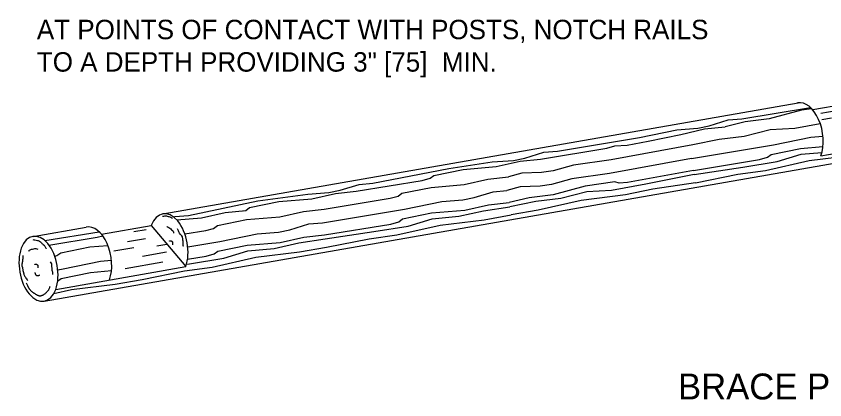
# Model space of a CAD drawing. Extents: x 49991 to 50288, y 49919 to 50011.
# Drawn here: x 50020.922 to 50023.528, y 49985.917 to 49987.153 of the extents above; entities that cross this region are included whole.
import ezdxf

# ---------------------------------------------------------------- set-up
doc = ezdxf.new("R2010")
doc.units = 0
doc.layers.add('Level 1', color=7, linetype='Continuous')
doc.layers.add('Level 2', color=7, linetype='Continuous')

msp = doc.modelspace()

# ---------------------------------------------------------------- linework, layer by layer
at = {"layer": 'Level 1'}
for p, q in [((50021.01237431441, 49986.23456588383), (50026.27076893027, 49987.15270974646)), ((50021.39464107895, 49986.51584634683), (50023.44173309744, 49986.873468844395)), ((50023.65085953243, 49986.878920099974), (50023.48937606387, 49986.850725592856)), ((50023.65298090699, 49986.863473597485), (50023.51549670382, 49986.839411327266)), ((50023.549503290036, 49986.82367427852), (50023.51885112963, 49986.81836657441)), ((50023.51548171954, 49986.702846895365), (50023.76174656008, 49986.745867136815)), ((50020.97702824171, 49986.44337197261), (50021.147483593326, 49986.473151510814)), ((50021.196921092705, 49986.45022108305), (50021.357590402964, 49986.47828976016)), ((50021.357590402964, 49986.47828976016), (50021.46864324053, 49986.34571894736)), ((50021.301555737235, 49986.45871434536), (50021.34095291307, 49986.4656606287)), ((50021.28090016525, 49986.42621710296), (50021.33879660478, 49986.436373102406)), ((50021.37569190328, 49986.412992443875), (50021.40757901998, 49986.41861501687)), ((50021.23709514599, 49986.39673294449), (50021.30092255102, 49986.407883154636)), ((50021.32977004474, 49986.37982644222), (50021.406914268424, 49986.39330485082)), ((50021.04959695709, 49986.272512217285), (50021.46864324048, 49986.34571894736)), ((50021.27350002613, 49986.339785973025), (50021.39434734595, 49986.36100572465))]:
    msp.add_line(p, q, dxfattribs=at)
for points in [[(50023.48609654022, 49986.854358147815), (50023.45255549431, 49986.8495782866), (50023.34908352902, 49986.82180914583), (50023.27121411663, 49986.81229836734), (50023.20670810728, 49986.79626866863)], [(50023.26098381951, 49986.82190900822), (50023.482077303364, 49986.85843118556)], [(50022.66652195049, 49986.71817836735), (50022.93076741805, 49986.76176230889), (50023.05090739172, 49986.78677876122), (50023.11917129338, 49986.79196925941), (50023.15539182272, 49986.799551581), (50023.2167627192, 49986.818467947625), (50023.26098381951, 49986.82190900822)], [(50022.61215795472, 49986.69239057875), (50022.825438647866, 49986.727613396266), (50022.85113049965, 49986.734753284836), (50022.89068484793, 49986.737631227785), (50022.95827289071, 49986.74997057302), (50023.06399196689, 49986.772005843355), (50023.14047937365, 49986.78945901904), (50023.20670810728, 49986.79626866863)], [(50023.513478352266, 49986.80624281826), (50023.431741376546, 49986.79107544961), (50023.35156822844, 49986.78674985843), (50023.26799229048, 49986.765031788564), (50023.18723492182, 49986.75504675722), (50023.10318851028, 49986.73849789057)], [(50023.097965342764, 49986.69451279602), (50023.36220367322, 49986.7381651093), (50023.482507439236, 49986.76326777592), (50023.522079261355, 49986.7662235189)], [(50023.10318851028, 49986.73849789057), (50022.83977171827, 49986.689954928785), (50022.717983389, 49986.67278395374), (50022.65226282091, 49986.6544848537), (50022.61556240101, 49986.649513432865), (50022.55150657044, 49986.646386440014), (50022.50870316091, 49986.634661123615)], [(50023.104696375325, 49986.65585343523), (50023.31792297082, 49986.69093237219), (50023.34361482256, 49986.69807226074), (50023.35560455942, 49986.707030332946), (50023.44973187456, 49986.72632486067), (50023.52209478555, 49986.73247231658)], [(50022.071975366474, 49986.61426609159), (50022.31611041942, 49986.662230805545), (50022.45648684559, 49986.682983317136), (50022.52468594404, 49986.68813249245), (50022.56093709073, 49986.69575256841), (50022.62216767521, 49986.71468884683), (50022.66652195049, 49986.71817836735)], [(50023.10690498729, 49986.642640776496), (50023.263635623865, 49986.666396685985), (50023.37449895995, 49986.6846044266), (50023.4514986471, 49986.707744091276), (50023.5188752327, 49986.713935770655)], [(50023.111541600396, 49986.61610012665), (50023.24813982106, 49986.64335295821), (50023.337355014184, 49986.655741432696), (50023.4776308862, 49986.68749060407), (50023.61869119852, 49986.70477258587), (50023.70588306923, 49986.71999099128)], [(50022.017604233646, 49986.58854667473), (50022.23091554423, 49986.62380724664), (50022.25661096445, 49986.630912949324), (50022.2686078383, 49986.63980264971), (50022.36263616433, 49986.65905228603), (50022.469479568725, 49986.66809713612), (50022.54603534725, 49986.68555744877), (50022.61215795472, 49986.69239057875)], [(50023.097965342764, 49986.69451279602), (50022.83452150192, 49986.64589789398), (50022.71279797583, 49986.62876824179), (50022.6470396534, 49986.6104997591), (50022.610308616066, 49986.6054905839), (50022.54634463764, 49986.60247685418), (50022.5035248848, 49986.59057703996)], [(50023.104696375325, 49986.65585343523), (50022.8921515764, 49986.61656043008), (50022.86550708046, 49986.61457397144), (50022.85132864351, 49986.618968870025), (50022.75617881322, 49986.60516606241), (50022.652741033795, 49986.57740049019), (50022.57479968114, 49986.5679167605), (50022.51032072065, 49986.55195900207)], [(50021.91419789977, 49986.5306840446), (50022.127399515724, 49986.56600228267), (50022.153204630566, 49986.57305031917), (50022.16508824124, 49986.58203187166), (50022.25926044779, 49986.6012274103), (50022.36603548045, 49986.61026512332), (50022.442553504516, 49986.627756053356), (50022.50870316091, 49986.634661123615)], [(50023.10690498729, 49986.642640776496), (50022.95162023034, 49986.61198588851), (50022.84113986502, 49986.59143359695), (50022.76089834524, 49986.587100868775), (50022.677397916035, 49986.56532156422), (50022.59652728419, 49986.55542838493), (50022.51259413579, 49986.538787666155)], [(50021.47742164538, 49986.510422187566), (50021.700740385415, 49986.557286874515), (50021.86194026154, 49986.57907104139), (50021.93020059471, 49986.58429572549), (50021.96637980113, 49986.591942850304), (50022.027658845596, 49986.61074595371), (50022.071975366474, 49986.61426609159)], [(50023.111541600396, 49986.61610012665), (50022.97393627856, 49986.59551560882), (50022.88565831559, 49986.57679711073), (50022.743073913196, 49986.55921780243), (50022.604442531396, 49986.52760573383), (50022.51718585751, 49986.512346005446)], [(50021.65561845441, 49986.52518738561), (50021.66219755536, 49986.527049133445), (50021.67416024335, 49986.5359352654), (50021.76815795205, 49986.55514714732), (50021.87492941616, 49986.56421904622), (50021.95151224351, 49986.58175129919), (50022.017604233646, 49986.58854667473)], [(50021.9092033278, 49986.486826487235), (50022.173312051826, 49986.53039615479), (50022.29361224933, 49986.55553300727), (50022.36177002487, 49986.56074698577), (50022.398058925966, 49986.56833644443), (50022.45929664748, 49986.5872043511), (50022.5035248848, 49986.59057703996)], [(50021.91591088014, 49986.448061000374), (50022.12900073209, 49986.483125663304), (50022.15480791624, 49986.4904849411), (50022.16661958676, 49986.49949354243), (50022.260757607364, 49986.518685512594), (50022.36754691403, 49986.527586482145), (50022.44417106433, 49986.54505393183), (50022.51032072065, 49986.55195900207)], [(50021.43980093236, 49986.496058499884), (50021.519484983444, 49986.50275212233), (50021.596026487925, 49986.52034917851), (50021.66219755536, 49986.527049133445)], [(50021.46565793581, 49986.45096337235), (50021.53285293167, 49986.46209000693), (50021.55855192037, 49986.469161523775), (50021.57057941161, 49986.478088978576), (50021.664668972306, 49986.49741412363), (50021.77144043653, 49986.50648602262), (50021.848003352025, 49986.52387796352), (50021.91419789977, 49986.5306840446)], [(50021.918135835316, 49986.4350228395), (50022.07462360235, 49986.458787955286), (50022.185625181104, 49986.47666454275), (50022.262644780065, 49986.49994451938), (50022.34844153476, 49986.508001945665), (50022.42799139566, 49986.52591303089), (50022.51259413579, 49986.538787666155)], [(50021.42918031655, 49986.5057666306), (50021.43313217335, 49986.50697398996), (50021.47742164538, 49986.510422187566)], [(50021.92270407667, 49986.408475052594), (50022.05917269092, 49986.43564523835), (50022.148607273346, 49986.44791838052), (50022.28880049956, 49986.47979715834), (50022.42996336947, 49986.49708984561), (50022.51718585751, 49986.512346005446)], [(50021.47504547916, 49986.40936738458), (50021.57889150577, 49986.42660071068), (50021.69925650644, 49986.45177888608), (50021.76740150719, 49986.45678418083), (50021.80366899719, 49986.46457875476), (50021.864917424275, 49986.48334410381), (50021.9092033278, 49986.486826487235)], [(50021.0146080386, 49986.42954659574), (50021.18924756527, 49986.45836434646)], [(50021.0275168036, 49986.41532338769), (50021.182739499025, 49986.44092418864), (50021.20113320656, 49986.44481405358)], [(50021.47441530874, 49986.36950321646), (50021.534672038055, 49986.37944348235), (50021.560291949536, 49986.38661041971), (50021.57232657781, 49986.39546950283), (50021.666358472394, 49986.414684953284), (50021.773156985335, 49986.42382879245), (50021.849685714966, 49986.44121716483), (50021.91591088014, 49986.448061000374)], [(50021.471093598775, 49986.35343692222), (50021.48032345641, 49986.35483228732), (50021.59126586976, 49986.37294460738), (50021.6682548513, 49986.39618682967), (50021.754024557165, 49986.40417231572), (50021.83354380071, 49986.42204564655), (50021.918135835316, 49986.4350228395)], [(50021.04643401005, 49986.379242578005), (50021.053707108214, 49986.38125052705), (50021.06562490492, 49986.39023564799), (50021.159755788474, 49986.40949598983), (50021.21761705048, 49986.41436088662)], [(50021.32834476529, 49986.30475511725), (50021.46483479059, 49986.33172018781), (50021.55426937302, 49986.34399332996), (50021.69440700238, 49986.37607365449), (50021.83544383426, 49986.39324951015), (50021.92270407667, 49986.408475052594)], [(50021.05618481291, 49986.335953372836), (50021.073956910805, 49986.33888769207), (50021.19426781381, 49986.363921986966), (50021.229203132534, 49986.36660109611)], [(50021.0558551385, 49986.29909710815), (50021.067415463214, 49986.30786261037), (50021.161621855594, 49986.327061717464), (50021.22931728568, 49986.33278906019)], [(50021.04355354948, 49986.25935074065), (50021.10002777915, 49986.27221340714), (50021.241262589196, 49986.289479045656), (50021.32834476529, 49986.30475511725)]]:
    msp.add_lwpolyline(points, dxfattribs=at)
for centre, major_axis, ratio, start_param, end_param in [((50023.45999035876, 49986.769206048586), (-0.01831237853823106, 0.10428811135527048), 0.577493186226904, 3.925707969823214, 6.306125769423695), ((50021.41297472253, 49986.41161520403), (-0.01831237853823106, 0.10428811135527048), 0.577493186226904, 3.9315222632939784, 7.063530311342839), ((50021.167172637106, 49986.36913342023), (-0.01831237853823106, 0.10428811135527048), 0.577493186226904, 3.9254893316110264, 6.306125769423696), ((50020.994103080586, 49986.338889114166), (-0.01831237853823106, 0.10428811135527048), 0.577493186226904, 3.9256121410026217, 7.063370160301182), ((50020.99409216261, 49986.33885928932), (-0.018312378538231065, 0.10428811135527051), 0.5774931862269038, 0.7858875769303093, 3.9259797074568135)]:
    msp.add_ellipse(centre, major_axis=major_axis, ratio=ratio, start_param=start_param, end_param=end_param, dxfattribs=at)
for points in [[(50021.4262607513, 49986.49996708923), (50021.42279505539, 49986.50337218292), (50021.41277694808, 49986.506646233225), (50021.4071849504, 49986.508239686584), (50021.400074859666, 49986.50815410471), (50021.393523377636, 49986.50702096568)], [(50021.407833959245, 49986.47454390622), (50021.40970440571, 49986.47384063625), (50021.41766929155, 49986.47004123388), (50021.42319306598, 49986.4644664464), (50021.42794747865, 49986.459640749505), (50021.42944595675, 49986.453231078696)], [(50021.46131367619, 49986.41014571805), (50021.461186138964, 49986.41037431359), (50021.46063122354, 49986.42396694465), (50021.459334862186, 49986.431088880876), (50021.45804135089, 49986.441494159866), (50021.448748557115, 49986.45337983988), (50021.444344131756, 49986.46346038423), (50021.441841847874, 49986.46789912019)], [(50020.97638882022, 49986.43293535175), (50020.98261814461, 49986.431857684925), (50020.99049495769, 49986.43022626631), (50020.99501291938, 49986.4286589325), (50021.00006244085, 49986.42597210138), (50021.00344549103, 49986.4226966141), (50021.00680656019, 49986.4189695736), (50021.011951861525, 49986.41470305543), (50021.01360741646, 49986.41307883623), (50021.01587867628, 49986.409860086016), (50021.01812381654, 49986.40556729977), (50021.018671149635, 49986.403965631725)], [(50021.415862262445, 49986.42805861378), (50021.41618418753, 49986.42833690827), (50021.41635143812, 49986.42847472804), (50021.41643673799, 49986.428543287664), (50021.416523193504, 49986.42861160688), (50021.416780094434, 49986.42879039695), (50021.41704695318, 49986.428934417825), (50021.41760567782, 49986.42912878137), (50021.4187890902, 49986.42921720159), (50021.419995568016, 49986.42904693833), (50021.420583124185, 49986.428917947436), (50021.42114724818, 49986.42878806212), (50021.42152562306, 49986.42869908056), (50021.421901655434, 49986.42859872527), (50021.422642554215, 49986.42834220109), (50021.4233616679, 49986.42797510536), (50021.42371046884, 49986.427736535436), (50021.42388172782, 49986.42760112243), (50021.424050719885, 49986.427454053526), (50021.42448148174, 49986.42703870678), (50021.424871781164, 49986.42661233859), (50021.425516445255, 49986.42571975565), (50021.425955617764, 49986.42476273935), (50021.426089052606, 49986.4242558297), (50021.426160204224, 49986.42372772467), (50021.42622673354, 49986.42247789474), (50021.42624951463, 49986.421233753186), (50021.42623392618, 49986.419992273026), (50021.426185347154, 49986.4187504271), (50021.42614881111, 49986.41799255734), (50021.42611281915, 49986.41723475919), (50021.42607205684, 49986.416477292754), (50021.42602120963, 49986.41572041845)], [(50020.96197074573, 49986.39597049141), (50020.963600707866, 49986.39712651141), (50020.971208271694, 49986.401598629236), (50020.97892007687, 49986.40305410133), (50020.985580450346, 49986.40429152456), (50020.9917302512, 49986.401944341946)], [(50020.94415452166, 49986.38125041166), (50020.94408022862, 49986.377368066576), (50020.9440206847, 49986.37543090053), (50020.94385679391, 49986.3735020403), (50020.943075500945, 49986.367519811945), (50020.94223622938, 49986.3615484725), (50020.94171387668, 49986.35894275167), (50020.94105784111, 49986.356352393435), (50020.94050298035, 49986.353751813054), (50020.94033688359, 49986.35243969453), (50020.94029451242, 49986.35177927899), (50020.94028415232, 49986.3511154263), (50020.94057045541, 49986.34875185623), (50020.941213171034, 49986.3464399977), (50020.94196237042, 49986.344140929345), (50020.942298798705, 49986.34298402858), (50020.94256812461, 49986.34181572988), (50020.943358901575, 49986.337509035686), (50020.94415824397, 49986.33320388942), (50020.94555715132, 49986.32653750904), (50020.946390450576, 49986.323232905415), (50020.946860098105, 49986.321591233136), (50020.947372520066, 49986.319957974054), (50020.94925439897, 49986.31565872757), (50020.95172812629, 49986.311669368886), (50020.95910051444, 49986.30096556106)], [(50020.98240673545, 49986.35315038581), (50020.98245611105, 49986.353189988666), (50020.98254256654, 49986.353258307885), (50020.98279946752, 49986.35343709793), (50020.98306632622, 49986.3535811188), (50020.98362505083, 49986.35377548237), (50020.98391490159, 49986.35383108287), (50020.984209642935, 49986.35386568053), (50020.98480846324, 49986.353863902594), (50020.98511504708, 49986.35383402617), (50020.985417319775, 49986.35379729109), (50020.98571678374, 49986.35375129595), (50020.986014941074, 49986.35369363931), (50020.98660249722, 49986.353564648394), (50020.98716662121, 49986.35343476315), (50020.9875449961, 49986.353345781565), (50020.98792102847, 49986.3532454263), (50020.98866192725, 49986.352988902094), (50020.989381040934, 49986.352621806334), (50020.98972984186, 49986.35238323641), (50020.98990110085, 49986.352247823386), (50020.99007009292, 49986.3521007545), (50020.9905008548, 49986.35168540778), (50020.99089115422, 49986.35125903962), (50020.9912314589, 49986.35082731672), (50020.991387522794, 49986.35060080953), (50020.99153581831, 49986.35036645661), (50020.99178228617, 49986.34989950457), (50020.9919749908, 49986.34940944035), (50020.992108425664, 49986.34890253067), (50020.99217957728, 49986.3483744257), (50020.99224610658, 49986.34712459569), (50020.99226888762, 49986.34588045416), (50020.99225329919, 49986.344638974), (50020.99220472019, 49986.34339712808), (50020.992168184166, 49986.34263925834), (50020.99213219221, 49986.34188146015), (50020.992112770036, 49986.341502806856)], [(50021.03992094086, 49986.32057874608), (50021.040440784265, 49986.32532156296), (50021.03927663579, 49986.33030649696), (50021.03770640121, 49986.34237235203), (50021.03746867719, 49986.345569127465), (50021.0367895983, 49986.35485007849), (50021.03291129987, 49986.361177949)], [(50020.99700456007, 49986.31829528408), (50020.99678976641, 49986.31792793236), (50020.99667598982, 49986.317743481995), (50020.99661740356, 49986.31765104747), (50020.996557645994, 49986.31755846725), (50020.99637225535, 49986.317306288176), (50020.99616621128, 49986.31708379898), (50020.995700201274, 49986.316719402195), (50020.994608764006, 49986.31625351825), (50020.99341195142, 49986.3160250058), (50020.992814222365, 49986.31595732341), (50020.99223838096, 49986.31589805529), (50020.99185154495, 49986.315860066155), (50020.99146325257, 49986.31583359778), (50020.99067920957, 49986.31583708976), (50020.989880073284, 49986.315952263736), (50020.98947291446, 49986.31606539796), (50020.98926709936, 49986.31613824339), (50020.989059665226, 49986.31622285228), (50020.98851784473, 49986.31647681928), (50020.98801075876, 49986.316754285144), (50020.9871123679, 49986.317390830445), (50020.98638764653, 49986.31815472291), (50020.98609764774, 49986.318591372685), (50020.985859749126, 49986.319068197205), (50020.9853931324, 49986.32022956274), (50020.984969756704, 49986.321399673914), (50020.98458355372, 49986.32257965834), (50020.98422845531, 49986.32377064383), (50020.984018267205, 49986.32449969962), (50020.98380758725, 49986.325228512), (50020.98360152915, 49986.32595855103), (50020.98340520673, 49986.326691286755)], [(50020.95411301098, 49986.29398827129), (50020.95834914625, 49986.28485779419), (50020.95925035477, 49986.28302296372), (50020.96020924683, 49986.281218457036), (50020.961212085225, 49986.27943457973), (50020.96224513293, 49986.27766163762), (50020.96371303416, 49986.2753272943), (50020.96531821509, 49986.27309378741), (50020.96707386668, 49986.27097033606), (50020.968012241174, 49986.26995276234), (50020.96899318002, 49986.268966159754), (50020.972865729, 49986.26558765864), (50020.97695935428, 49986.26250589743), (50020.97955915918, 49986.26066457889), (50020.982184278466, 49986.25888740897), (50020.984850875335, 49986.25716621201), (50020.98757511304, 49986.25549281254), (50020.98920749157, 49986.25458759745), (50020.99087626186, 49986.253803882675), (50020.992613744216, 49986.253119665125), (50020.99351835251, 49986.252807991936), (50020.99445225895, 49986.25251294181), (50020.99606276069, 49986.252108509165), (50020.99766111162, 49986.25187784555), (50020.99924171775, 49986.25182797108), (50021.00002361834, 49986.251873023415), (50021.000798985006, 49986.251965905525), (50021.00287026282, 49986.252388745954), (50021.00491871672, 49986.253012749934), (50021.007924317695, 49986.254280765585), (50021.00890274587, 49986.25478164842), (50021.01067770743, 49986.25575364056), (50021.01238732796, 49986.25676956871), (50021.01560452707, 49986.25910984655), (50021.01695383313, 49986.26036780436), (50021.01827080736, 49986.26165222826), (50021.02083538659, 49986.26428669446), (50021.02191150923, 49986.26542934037), (50021.02300995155, 49986.26656100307), (50021.02516381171, 49986.26885463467), (50021.02707700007, 49986.27129410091), (50021.028529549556, 49986.27400591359), (50021.03014629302, 49986.27821043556), (50021.031662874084, 49986.282335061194)]]:
    msp.add_spline(points, degree=3, dxfattribs=at)

# ---------------------------------------------------------------- texts
at = {"layer": 'Level 2'}
for s, height, p in [('AT POINTS OF CONTACT WITH POSTS, NOTCH RAILS', 0.06264226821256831, (50020.98889550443, 49987.078452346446)), ('TO A DEPTH PROVIDING 3" [75]  MIN. ', 0.06264226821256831, (50020.98889550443, 49986.9740485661)), ('BRACE POLE NOTCHING', 0.08352302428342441, (50023.05499243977, 49985.917844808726))]:
    msp.add_text(s, height=height, dxfattribs=at).set_placement(p)

doc.saveas('drawing.dxf')
